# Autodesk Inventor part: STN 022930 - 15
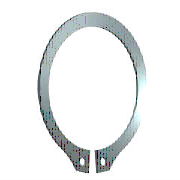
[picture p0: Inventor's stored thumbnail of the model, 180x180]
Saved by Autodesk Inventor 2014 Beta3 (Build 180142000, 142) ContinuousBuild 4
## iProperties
IsCustomPart: 0
Created: 2010-02
Part Number: STN 022930 - 15
Material: Steel, Mild
Description: Retaining rings for shaft
Document SubType Name: Modeling
Standard: STN 022930
Designer: Thom Tremblay
Standards Organization: STN
Language: en-US
Size Designation: 15
Categories: <MemberInstance><Categories><Category DisplayName="Shaft Parts" InternalName="7f7aeb1f-a693-4053-b835-cee3144e0d98" Mnemonic="SHFT"><Category DisplayName="Circl
Density: 7.86 g/cm^3
Appearance: Steel
Author: Thom Tremblay
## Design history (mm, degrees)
node "WorkPlane1"
workplane "Work Plane2"
node "WorkPlane2"
node "Sketch1"
node "WorkPoint1"
node "WorkAxis1"
sketch "Sketch3"
  geometry: L1 (-0.85, -7.099)-(-0.85, -10.599) reference; L2 (-0.85, -10.599)-(-4.25, -10) reference; 1 further point
  dimensions: "d30" = 1.36 distance from line of L1 point (-2.21, -8.76) (= 0.8 x Diam5); "d32" = 1.575 distance from line of L2 point (-2.21, -8.76) (= 0.45 x ParA)
hole "Hole1" sketch "Sketch3" at (-2.21, -8.76) diameter "d33" = 1.7 (= Diam5); stored, may be unused: countersink angle "d37" = 60 deg, drill point angle "d39" = 118 deg; dims "d34" = 6, "d35" = 4, "d36" = 2, "d38" = 8
sketch "Sketch4"
  geometry: L1 (0.85, -10.599)-(0.85, -7.099) reference; L2 (4.25, -10)-(0.85, -10.599) reference; 1 further point
  dimensions: "d41" = 1.36 distance from line of L1 point (2.21, -8.76) (= 0.8 x Diam5); "d43" = 1.575 distance from line of L2 point (2.21, -8.76) (= 0.45 x ParA)
hole "Hole2" sketch "Sketch4" at (2.21, -8.76) diameter "d44" = 1.7 (= Diam5); stored, may be unused: countersink angle "d48" = 60 deg, drill point angle "d50" = 118 deg; dims "d45" = 6, "d46" = 4, "d47" = 2, "d49" = 8
fillet "Fillet1" dims "d51" = 2.55 (= 1.5 x Diam5)
body "Solid1"
sketch "Sketch2"
  geometry: L1 (4.25, -10)-(4.25, -7.227); L2 (0.85, -10.599)-(4.25, -10); L3 (0.85, -7.099)-(0.85, -10.599); L4 (-0.85, -7.099)-(-0.85, -10.599); L5 (-0.85, -10.599)-(-4.25, -10); L6 (-4.25, -10)-(-4.25, -7.227); A1 r 7.15 centre (0, 0) between (0.85, -7.099) and (-0.85, -7.099); A2 r 8.833 centre (0, 0.517) between (4.25, -7.227) and (-4.25, -7.227); 1 further point
  constraints: 12 end point, 4 point on circle, 4 vertical, 2 centre point
  dimensions: "d2" = 7.15 radius of A1 (= 0.5 x Diam2); "d4" = 8.83333 radius of A2 (= 0.166667 x ParA + 0.5 x Diam2 + 0.5 x b); "d6" = 0 horizontal distance of A2.centre A1.centre; "d8" = 0.85 horizontal distance of L3.start A1.centre (= 0.5 x Diam5); "d10" = 0.85 horizontal distance of L4.start A1.centre (= 0.5 x Diam5); "d12" = 3.5 distance of L4.start L4.end (= ParA); "d14" = 3.5 distance of L3.start L2.start (= ParA); "d16" = 80 deg angle of L2 L3; "d18" = 80 deg angle of L4 L5; "d20" = 3.4 horizontal distance of L4.start L6.end (= 2 x Diam5); "d22" = 3.4 horizontal distance of L1.start L3.start (= 2 x Diam5); "d24" = 0.51667 distance of A1.centre A2.centre (= -msp_r2 + 0.5 x Diam2 + b); "d52" = 0 distance of point (0, 0) A1.centre; "d53" = 0 distance of A1.centre point (0, 0)
extrude "Extrusion1" new body sketch "Sketch2" distance "d25" = 1 (= ParS); taper "d26" = 0 deg
other parameters: "Diam5" = 1.7 [user parameter; used in 9 equation terms], "ParA" = 3.5 [user parameter; used in 6 equation terms], "b" = 2.2 [user parameter; used in 3 equation terms], "ParS" = 1 [user parameter; used in 2 equation terms], "Diam2" = 14.3 [user parameter; used in 4 equation terms], "msp_r2" = 8.83333 (= 0.166667 x ParA + 0.5 x Diam2 + 0.5 x b) [user parameter; used in 1 equation term], "d0" = -1 (computed from ParS), "d1" = 14.3 (derived), "d3" = 0, "d5" = 0 (derived), "d7" = 1 (derived), "d9" = 1 (derived), "d11" = 4.8 (derived), "d13" = 4.8 (derived), "d15" = 80 deg (derived), "d17" = 80 deg (derived), "d19" = 4 (derived), "d21" = 4 (derived), "d23" = 0.95 (derived), "d27" = 0, "d28" = 0, "d29" = 1.6 (derived), "d31" = 2.16 (derived), "d40" = 1.6 (derived), "d42" = 2.16 (derived), "d55" = 0, "d56" = 0, "d57" = 0, "d58" = 0, "TEMPLATE" = 12.345 [user parameter]
